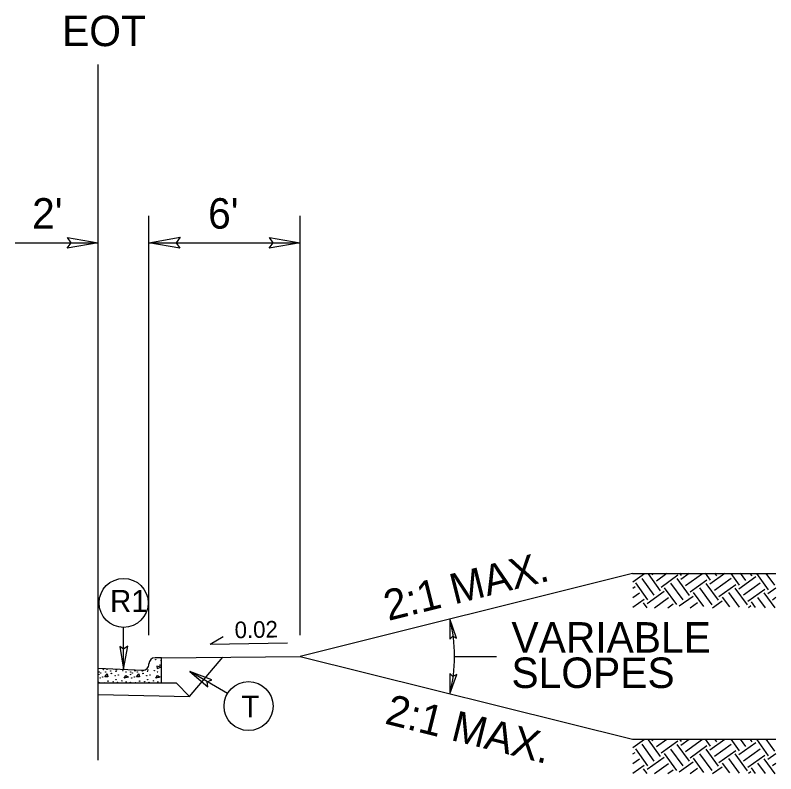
# Model space of a CAD drawing. Extents: x 3025871 to 3026431, y 707165 to 707825.
# Drawn here: x 3025870.79 to 3025900.94, y 707599.56 to 707629.66 of the extents above; entities that cross this region are included whole.
import ezdxf

# ---------------------------------------------------------------- set-up
doc = ezdxf.new("R2010")
doc.units = 0
for name, color, linetype in [('Prop Drainage Structure Junction Box with Manhole CELL', 7, 'Continuous'), ('Prop Drainage Structure Junction Box with Slab Lid TB 840 34 CELL', 7, 'Continuous'), ('Prop Drainage Structure Plot Symbol 50 Scale', 7, 'Continuous'), ('Sheet Plot Border Inside CELL', 7, 'Continuous'), ('Sheet Sticker Incomplete CELL', 7, 'Continuous'), ('Sheet Typical CELL', 7, 'Continuous'), ('Typical Arrow Superelevation CELL', 7, 'Continuous'), ('Typical Grade Point Symbol CELL', 7, 'Continuous'), ('Typical Shoulder Slope CELL', 7, 'Continuous'), ('Typical Text Centerline CELL', 7, 'Continuous'), ('Typical Text Grade Point CELL', 7, 'Continuous')]:
    doc.layers.add(name, color=color, linetype=linetype)

msp = doc.modelspace()

# ---------------------------------------------------------------- linework, layer by layer
at = {"layer": 'Prop Drainage Structure Junction Box with Manhole CELL'}
msp.add_line((3025874.084, 707602.705), (3025877.694, 707602.633), dxfattribs=at)
at = {"layer": 'Prop Drainage Structure Junction Box with Slab Lid TB 840 34 CELL'}
for p, q in [((3025876.092, 707605.059), (3025876.092, 707621.699)), ((3025882.092, 707605.059), (3025882.092, 707621.699)), ((3025870.789, 707620.632), (3025874.084, 707620.632)), ((3025876.092, 707620.632), (3025882.092, 707620.632)), ((3025888.208, 707604.219), (3025889.863, 707604.219))]:
    msp.add_line(p, q, dxfattribs=at)
msp.add_arc((3025882.092, 707604.219), 6.116, 345.9638, 14.0362, dxfattribs=at)
at = {"layer": 'Prop Drainage Structure Plot Symbol 50 Scale'}
for p, q in [((3025876.592, 707604.165), (3025876.331, 707604.165)), ((3025876.592, 707603.162), (3025876.592, 707604.165)), ((3025876.091, 707603.914), (3025876.091, 707603.925)), ((3025874.084, 707603.162), (3025874.084, 707603.747)), ((3025874.084, 707603.747), (3025875.84, 707603.674)), ((3025876.401, 707603.831), (3025876.418, 707603.74)), ((3025876.556, 707603.786), (3025876.401, 707603.831)), ((3025876.418, 707603.74), (3025876.556, 707603.786)), ((3025874.345, 707603.402), (3025874.432, 707603.522)), ((3025874.466, 707603.408), (3025874.345, 707603.402)), ((3025874.432, 707603.522), (3025874.466, 707603.408)), ((3025875.113, 707603.351), (3025875.176, 707603.466)), ((3025875.279, 707603.391), (3025875.113, 707603.351)), ((3025875.176, 707603.466), (3025875.279, 707603.391)), ((3025875.599, 707603.402), (3025875.685, 707603.522)), ((3025875.719, 707603.408), (3025875.599, 707603.402)), ((3025875.685, 707603.522), (3025875.719, 707603.408)), ((3025876.366, 707603.351), (3025876.429, 707603.466)), ((3025876.533, 707603.391), (3025876.366, 707603.351)), ((3025876.429, 707603.466), (3025876.533, 707603.391)), ((3025876.592, 707603.162), (3025874.084, 707603.162))]:
    msp.add_line(p, q, dxfattribs=at)
for centre in [(3025876.361, 707604.089), (3025876.527, 707603.871), (3025876.579, 707604.055), (3025874.117, 707603.597), (3025874.173, 707603.563), (3025874.282, 707603.688), (3025874.38, 707603.603), (3025874.426, 707603.705), (3025874.575, 707603.642), (3025874.781, 707603.626), (3025874.798, 707603.677), (3025875.056, 707603.648), (3025875.176, 707603.597), (3025875.371, 707603.597), (3025875.427, 707603.563), (3025875.536, 707603.646), (3025875.633, 707603.603), (3025875.828, 707603.642), (3025876.034, 707603.626), (3025876.052, 707603.677), (3025876.309, 707603.648), (3025876.43, 707603.597), (3025874.1, 707603.5), (3025874.157, 707603.357), (3025874.254, 707603.402), (3025874.603, 707603.54), (3025874.752, 707603.454), (3025874.786, 707603.299), (3025874.878, 707603.483), (3025875.021, 707603.248), (3025875.354, 707603.5), (3025875.411, 707603.357), (3025875.507, 707603.402), (3025875.857, 707603.54), (3025876.006, 707603.454), (3025876.04, 707603.299), (3025876.132, 707603.483), (3025876.275, 707603.248), (3025874.094, 707603.19), (3025874.305, 707603.168), (3025874.466, 707603.236), (3025874.672, 707603.213), (3025874.844, 707603.185), (3025875.193, 707603.208), (3025875.348, 707603.19), (3025875.559, 707603.168), (3025875.719, 707603.236), (3025875.926, 707603.213), (3025876.098, 707603.185), (3025876.447, 707603.208)]:
    msp.add_circle(centre, 0.00805, dxfattribs=at)
for centre, start, end in [((3025876.331, 707603.925), 90, 180), ((3025875.85, 707603.914), 267.6155, 0)]:
    msp.add_arc(centre, 0.24, start, end, dxfattribs=at)
at = {"layer": 'Sheet Plot Border Inside CELL'}
msp.add_line((3025877.177, 707603.15), (3025876.592, 707603.162), dxfattribs=at)
at = {"layer": 'Sheet Sticker Incomplete CELL'}
for q in [(3025879.028, 707605.011), (3025881.581, 707604.761)]:
    msp.add_line((3025878.513, 707604.7), q, dxfattribs=at)
at = {"layer": 'Sheet Typical CELL'}
for p, q in [((3025876.592, 707604.165), (3025882.092, 707604.219)), ((3025877.694, 707602.633), (3025879.017, 707604.189)), ((3025877.177, 707603.15), (3025877.694, 707602.633))]:
    msp.add_line(p, q, dxfattribs=at)
at = {"layer": 'Typical Grade Point Symbol CELL'}
for p, q in [((3025875.088, 707603.705), (3025875.088, 707605.367)), ((3025879.203, 707602.741), (3025877.718, 707603.617))]:
    msp.add_line(p, q, dxfattribs=at)
for centre in [(3025875.088, 707606.339), (3025880.04, 707602.247)]:
    msp.add_circle(centre, 0.972, dxfattribs=at)
at = {"layer": 'Typical Shoulder Slope CELL'}
msp.add_line((3025874.084, 707600.106), (3025874.084, 707627.699), dxfattribs=at)
at = {"layer": 'Typical Text Centerline CELL'}
for points in [[(3025872.858, 707620.843), (3025874.084, 707620.632), (3025872.852, 707620.415), (3025873.008, 707620.632)], [(3025877.317, 707620.421), (3025876.092, 707620.632), (3025877.324, 707620.85), (3025877.168, 707620.632)], [(3025880.867, 707620.843), (3025882.092, 707620.632), (3025880.86, 707620.415), (3025881.017, 707620.632)], [(3025888.288, 707604.945), (3025888.025, 707605.702), (3025888.016, 707604.896), (3025888.138, 707605.018)], [(3025874.931, 707604.615), (3025875.088, 707603.705), (3025875.25, 707604.62), (3025875.088, 707604.504)], [(3025878.581, 707603.29), (3025877.718, 707603.617), (3025878.423, 707603.013), (3025878.405, 707603.212)], [(3025888.022, 707603.537), (3025888.025, 707602.736), (3025888.295, 707603.496), (3025888.14, 707603.42)]]:
    msp.add_lwpolyline(points, close=True, dxfattribs=at)
at = {"layer": 'Typical Text Grade Point CELL'}
for p, q in [((3025895.257, 707607.51), (3025882.092, 707604.219)), ((3025895.257, 707607.51), (3025900.942, 707607.51)), ((3025895.257, 707607.51), (3025900.942, 707607.51)), ((3025895.279, 707607.181), (3025895.739, 707607.511)), ((3025895.279, 707607.181), (3025895.739, 707607.511)), ((3025896.369, 707606.824), (3025895.889, 707607.493)), ((3025896.369, 707606.824), (3025895.889, 707607.493)), ((3025896.033, 707607.469), (3025896.093, 707607.512)), ((3025896.033, 707607.469), (3025896.093, 707607.512)), ((3025896.213, 707607.218), (3025896.624, 707607.514)), ((3025896.213, 707607.218), (3025896.624, 707607.514)), ((3025897.205, 707607.425), (3025897.14, 707607.515)), ((3025897.205, 707607.425), (3025897.14, 707607.515)), ((3025897.181, 707607.281), (3025897.509, 707607.516)), ((3025897.181, 707607.281), (3025897.509, 707607.516)), ((3025897.361, 707607.03), (3025898.03, 707607.511)), ((3025897.361, 707607.03), (3025898.03, 707607.511)), ((3025898.354, 707607.237), (3025898.151, 707607.518)), ((3025898.354, 707607.237), (3025898.151, 707607.518)), ((3025898.33, 707607.093), (3025898.925, 707607.521)), ((3025898.33, 707607.093), (3025898.925, 707607.521)), ((3025898.604, 707607.417), (3025898.53, 707607.519)), ((3025898.604, 707607.417), (3025898.53, 707607.519)), ((3025899.502, 707607.048), (3025899.17, 707607.51)), ((3025899.502, 707607.048), (3025899.17, 707607.51)), ((3025899.753, 707607.229), (3025899.542, 707607.522)), ((3025899.753, 707607.229), (3025899.542, 707607.522)), ((3025900.004, 707607.409), (3025899.931, 707607.51)), ((3025900.004, 707607.409), (3025899.931, 707607.51)), ((3025900.651, 707606.86), (3025900.184, 707607.51)), ((3025900.651, 707606.86), (3025900.184, 707607.51)), ((3025900.902, 707607.041), (3025900.564, 707607.51)), ((3025900.902, 707607.041), (3025900.564, 707607.51)), ((3025896.119, 707606.644), (3025895.638, 707607.312)), ((3025896.119, 707606.644), (3025895.638, 707607.312)), ((3025896.393, 707606.968), (3025897.061, 707607.448)), ((3025896.393, 707606.968), (3025897.061, 707607.448)), ((3025897.518, 707606.636), (3025897.038, 707607.305)), ((3025897.518, 707606.636), (3025897.038, 707607.305)), ((3025897.542, 707606.78), (3025898.21, 707607.26)), ((3025897.542, 707606.78), (3025898.21, 707607.26)), ((3025898.51, 707606.842), (3025899.179, 707607.323)), ((3025898.51, 707606.842), (3025899.179, 707607.323)), ((3025899.479, 707606.905), (3025900.147, 707607.385)), ((3025899.479, 707606.905), (3025900.147, 707607.385)), ((3025895.279, 707606.928), (3025895.364, 707606.989)), ((3025895.279, 707606.928), (3025895.364, 707606.989)), ((3025895.868, 707606.464), (3025895.388, 707607.132)), ((3025895.868, 707606.464), (3025895.388, 707607.132)), ((3025897.017, 707606.276), (3025896.536, 707606.944)), ((3025897.017, 707606.276), (3025896.536, 707606.944)), ((3025897.267, 707606.456), (3025896.787, 707607.124)), ((3025897.267, 707606.456), (3025896.787, 707607.124)), ((3025898.416, 707606.268), (3025897.936, 707606.936)), ((3025898.416, 707606.268), (3025897.936, 707606.936)), ((3025898.667, 707606.448), (3025898.186, 707607.116)), ((3025898.667, 707606.448), (3025898.186, 707607.116)), ((3025898.69, 707606.592), (3025899.359, 707607.072)), ((3025898.69, 707606.592), (3025899.359, 707607.072)), ((3025899.816, 707606.26), (3025899.335, 707606.928)), ((3025899.816, 707606.26), (3025899.335, 707606.928)), ((3025899.659, 707606.654), (3025900.327, 707607.135)), ((3025899.659, 707606.654), (3025900.327, 707607.135)), ((3025899.839, 707606.404), (3025900.507, 707606.884)), ((3025899.839, 707606.404), (3025900.507, 707606.884)), ((3025900.627, 707606.717), (3025900.942, 707606.943)), ((3025900.627, 707606.717), (3025900.942, 707606.943)), ((3025895.279, 707606.548), (3025895.544, 707606.738)), ((3025895.279, 707606.548), (3025895.544, 707606.738)), ((3025895.845, 707606.32), (3025896.513, 707606.801)), ((3025895.845, 707606.32), (3025896.513, 707606.801)), ((3025897.113, 707606.218), (3025897.662, 707606.613)), ((3025897.113, 707606.218), (3025897.662, 707606.613)), ((3025898.086, 707606.199), (3025897.685, 707606.756)), ((3025898.086, 707606.199), (3025897.685, 707606.756)), ((3025899.5, 707606.17), (3025899.085, 707606.748)), ((3025899.5, 707606.17), (3025899.085, 707606.748)), ((3025900.914, 707606.142), (3025900.484, 707606.74)), ((3025900.914, 707606.142), (3025900.484, 707606.74)), ((3025895.279, 707606.167), (3025895.724, 707606.487)), ((3025895.279, 707606.167), (3025895.724, 707606.487)), ((3025895.84, 707606.15), (3025895.701, 707606.344)), ((3025895.84, 707606.15), (3025895.701, 707606.344)), ((3025896.137, 707606.15), (3025896.693, 707606.55)), ((3025896.137, 707606.15), (3025896.693, 707606.55)), ((3025896.666, 707606.15), (3025896.873, 707606.299)), ((3025896.666, 707606.15), (3025896.873, 707606.299)), ((3025897.547, 707606.15), (3025897.842, 707606.362)), ((3025897.547, 707606.15), (3025897.842, 707606.362)), ((3025898.429, 707606.15), (3025898.81, 707606.425)), ((3025898.429, 707606.15), (3025898.81, 707606.425)), ((3025899.114, 707606.178), (3025898.834, 707606.568)), ((3025899.114, 707606.178), (3025898.834, 707606.568)), ((3025900.143, 707606.157), (3025899.983, 707606.38)), ((3025900.143, 707606.157), (3025899.983, 707606.38)), ((3025900.528, 707606.15), (3025900.233, 707606.56)), ((3025900.528, 707606.15), (3025900.233, 707606.56)), ((3025900.808, 707606.466), (3025900.942, 707606.563)), ((3025900.808, 707606.466), (3025900.942, 707606.563)), ((3025899.857, 707606.163), (3025899.959, 707606.236)), ((3025899.857, 707606.163), (3025899.959, 707606.236)), ((3025882.092, 707604.219), (3025895.257, 707600.928)), ((3025895.257, 707600.928), (3025900.942, 707600.928)), ((3025895.257, 707600.928), (3025900.942, 707600.928)), ((3025895.279, 707600.598), (3025895.739, 707600.929)), ((3025895.279, 707600.598), (3025895.739, 707600.929)), ((3025896.369, 707600.242), (3025895.889, 707600.91)), ((3025896.369, 707600.242), (3025895.889, 707600.91)), ((3025896.033, 707600.886), (3025896.093, 707600.93)), ((3025896.033, 707600.886), (3025896.093, 707600.93)), ((3025896.213, 707600.636), (3025896.624, 707600.931)), ((3025896.213, 707600.636), (3025896.624, 707600.931)), ((3025896.393, 707600.385), (3025897.061, 707600.866)), ((3025896.393, 707600.385), (3025897.061, 707600.866)), ((3025897.205, 707600.842), (3025897.14, 707600.933)), ((3025897.205, 707600.842), (3025897.14, 707600.933)), ((3025897.181, 707600.698), (3025897.509, 707600.934)), ((3025897.181, 707600.698), (3025897.509, 707600.934)), ((3025897.361, 707600.448), (3025898.03, 707600.928)), ((3025897.361, 707600.448), (3025898.03, 707600.928)), ((3025898.354, 707600.654), (3025898.151, 707600.936)), ((3025898.354, 707600.654), (3025898.151, 707600.936)), ((3025898.33, 707600.51), (3025898.925, 707600.938)), ((3025898.33, 707600.51), (3025898.925, 707600.938)), ((3025898.604, 707600.834), (3025898.53, 707600.937)), ((3025898.604, 707600.834), (3025898.53, 707600.937)), ((3025899.502, 707600.466), (3025899.17, 707600.928)), ((3025899.502, 707600.466), (3025899.17, 707600.928)), ((3025899.753, 707600.646), (3025899.542, 707600.94)), ((3025899.753, 707600.646), (3025899.542, 707600.94)), ((3025900.004, 707600.826), (3025899.931, 707600.928)), ((3025900.004, 707600.826), (3025899.931, 707600.928)), ((3025900.651, 707600.278), (3025900.184, 707600.928)), ((3025900.651, 707600.278), (3025900.184, 707600.928)), ((3025900.902, 707600.458), (3025900.564, 707600.928)), ((3025900.902, 707600.458), (3025900.564, 707600.928)), ((3025895.868, 707599.881), (3025895.388, 707600.55)), ((3025895.868, 707599.881), (3025895.388, 707600.55)), ((3025896.119, 707600.061), (3025895.638, 707600.73)), ((3025896.119, 707600.061), (3025895.638, 707600.73)), ((3025897.267, 707599.873), (3025896.787, 707600.542)), ((3025897.267, 707599.873), (3025896.787, 707600.542)), ((3025897.518, 707600.054), (3025897.038, 707600.722)), ((3025897.518, 707600.054), (3025897.038, 707600.722)), ((3025897.542, 707600.197), (3025898.21, 707600.677)), ((3025897.542, 707600.197), (3025898.21, 707600.677)), ((3025898.51, 707600.26), (3025899.179, 707600.74)), ((3025898.51, 707600.26), (3025899.179, 707600.74)), ((3025899.479, 707600.322), (3025900.147, 707600.803)), ((3025899.479, 707600.322), (3025900.147, 707600.803)), ((3025899.659, 707600.072), (3025900.327, 707600.552)), ((3025899.659, 707600.072), (3025900.327, 707600.552)), ((3025895.279, 707600.345), (3025895.364, 707600.406)), ((3025895.279, 707600.345), (3025895.364, 707600.406)), ((3025897.017, 707599.693), (3025896.536, 707600.362)), ((3025897.017, 707599.693), (3025896.536, 707600.362)), ((3025898.416, 707599.685), (3025897.936, 707600.354)), ((3025898.416, 707599.685), (3025897.936, 707600.354)), ((3025898.667, 707599.865), (3025898.186, 707600.534)), ((3025898.667, 707599.865), (3025898.186, 707600.534)), ((3025898.69, 707600.009), (3025899.359, 707600.489)), ((3025898.69, 707600.009), (3025899.359, 707600.489)), ((3025899.816, 707599.677), (3025899.335, 707600.346)), ((3025899.816, 707599.677), (3025899.335, 707600.346)), ((3025899.839, 707599.821), (3025900.507, 707600.301)), ((3025899.839, 707599.821), (3025900.507, 707600.301)), ((3025900.627, 707600.134), (3025900.942, 707600.36)), ((3025900.627, 707600.134), (3025900.942, 707600.36)), ((3025895.279, 707599.965), (3025895.544, 707600.156)), ((3025895.279, 707599.965), (3025895.544, 707600.156)), ((3025895.845, 707599.738), (3025896.513, 707600.218)), ((3025895.845, 707599.738), (3025896.513, 707600.218)), ((3025896.137, 707599.568), (3025896.693, 707599.967)), ((3025896.137, 707599.568), (3025896.693, 707599.967)), ((3025897.113, 707599.636), (3025897.662, 707600.03)), ((3025897.113, 707599.636), (3025897.662, 707600.03)), ((3025898.086, 707599.616), (3025897.685, 707600.174)), ((3025898.086, 707599.616), (3025897.685, 707600.174)), ((3025899.114, 707599.595), (3025898.834, 707599.986)), ((3025899.114, 707599.595), (3025898.834, 707599.986)), ((3025899.5, 707599.588), (3025899.085, 707600.166)), ((3025899.5, 707599.588), (3025899.085, 707600.166)), ((3025900.528, 707599.567), (3025900.233, 707599.978)), ((3025900.528, 707599.567), (3025900.233, 707599.978)), ((3025900.914, 707599.559), (3025900.484, 707600.158)), ((3025900.914, 707599.559), (3025900.484, 707600.158)), ((3025900.808, 707599.884), (3025900.942, 707599.98)), ((3025900.808, 707599.884), (3025900.942, 707599.98)), ((3025895.279, 707599.585), (3025895.724, 707599.905)), ((3025895.279, 707599.585), (3025895.724, 707599.905)), ((3025895.84, 707599.568), (3025895.701, 707599.761)), ((3025895.84, 707599.568), (3025895.701, 707599.761)), ((3025896.666, 707599.568), (3025896.873, 707599.717)), ((3025896.666, 707599.568), (3025896.873, 707599.717)), ((3025897.547, 707599.568), (3025897.842, 707599.779)), ((3025897.547, 707599.568), (3025897.842, 707599.779)), ((3025898.429, 707599.568), (3025898.81, 707599.842)), ((3025898.429, 707599.568), (3025898.81, 707599.842)), ((3025899.857, 707599.58), (3025899.959, 707599.654)), ((3025899.857, 707599.58), (3025899.959, 707599.654)), ((3025900.143, 707599.575), (3025899.983, 707599.797)), ((3025900.143, 707599.575), (3025899.983, 707599.797))]:
    msp.add_line(p, q, dxfattribs=at)

# ---------------------------------------------------------------- texts
at = {"layer": 'Prop Drainage Structure Junction Box with Slab Lid TB 840 34 CELL'}
for s, p in [('EOT', (3025872.646, 707628.432)), ("2'", (3025871.458, 707621.191)), ("6'", (3025878.435, 707621.191))]:
    msp.add_text(s, height=1.2089, dxfattribs=at).set_placement(p)
at = {"layer": 'Sheet Sticker Incomplete CELL'}
msp.add_text('0.02 ', height=0.6583, rotation=1.2029, dxfattribs=at).set_placement((3025879.494, 707604.935))
at = {"layer": 'Typical Arrow Superelevation CELL'}
for s, p in [('R1', (3025874.55, 707605.982)), ('T', (3025879.756, 707601.796))]:
    msp.add_text(s, height=0.87, rotation=360, dxfattribs=at).set_placement(p)
at = {"layer": 'Typical Text Grade Point CELL'}
for rotation, p in [(14.0362, (3025885.579, 707605.621)), (345.9638, (3025885.4, 707601.561))]:
    msp.add_text('2:1 MAX.', height=1.2089, rotation=rotation, dxfattribs=at).set_placement(p)
for s, p in [('VARIABLE', (3025890.462, 707604.367)), ('SLOPES', (3025890.462, 707602.965))]:
    msp.add_text(s, height=1.2089, dxfattribs=at).set_placement(p)

doc.saveas('drawing.dxf')
